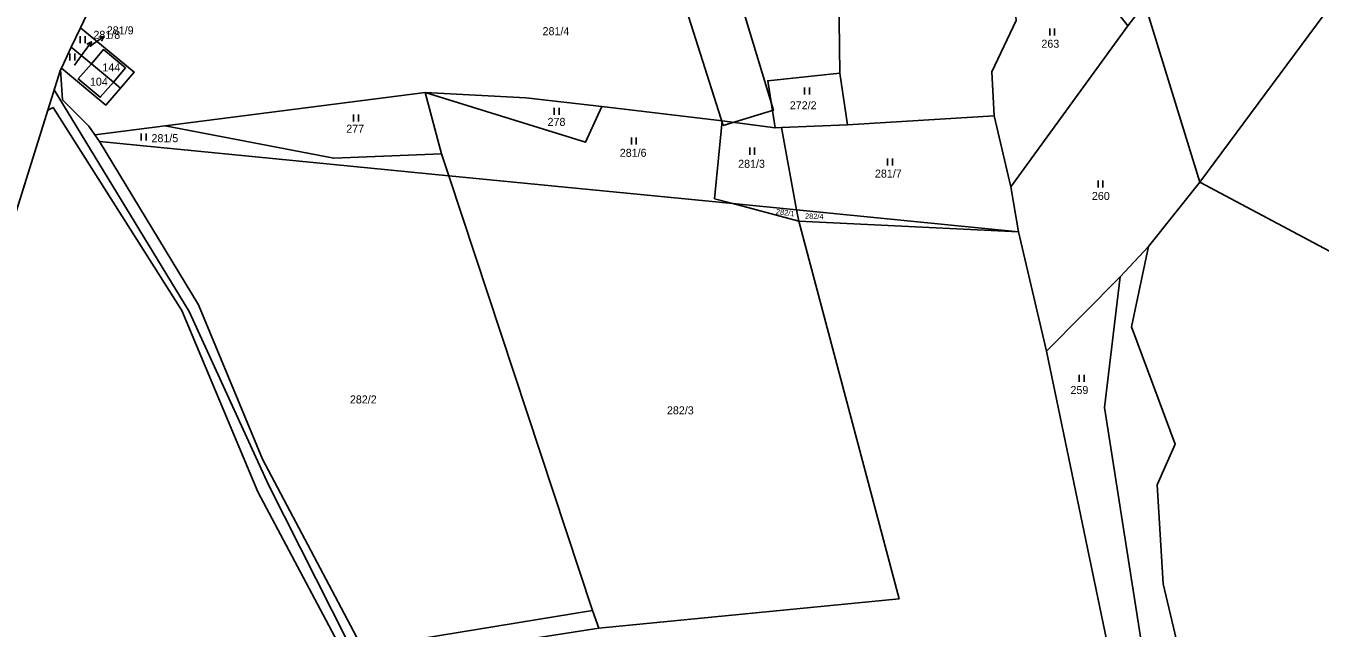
# Model space of a CAD drawing. Extents: x -590606 to -587796, y -1065936 to -1062515.
# Drawn here: x -589191 to -588916, y -1064752.6 to -1064624.7 of the extents above; entities that cross this region are included whole.
import ezdxf

# ---------------------------------------------------------------- set-up
doc = ezdxf.new("R2010")
doc.units = 0
for name, color, linetype in [('Cesty', 7, 'Continuous'), ('Parcela nároku', 7, 'Continuous'), ('Parcelní číslo', 7, 'Continuous'), ('Tok', 7, 'Continuous'), ('Vnější obvod_ Studené', 7, 'Continuous'), ('Vrstva 30', 7, 'Continuous')]:
    doc.layers.add(name, color=color, linetype=linetype)

msp = doc.modelspace()

# ---------------------------------------------------------------- linework, layer by layer
at = {"layer": 'Cesty'}
msp.add_lwpolyline([(-589184.99, -1064638.29), (-589156.28, -1064685.35), (-589139.47, -1064722.15), (-589122.5, -1064755.61), (-589105.35, -1064782.5), (-589087.98, -1064799.87), (-589067.31, -1064825.55), (-589029.84, -1064877.89), (-589010.25, -1064901.8), (-588993.22, -1064919.79), (-588983.42, -1064935.93), (-588980.16, -1064951.16), (-588977.69, -1065009.91), (-588977.48, -1065046.76), (-588981.79, -1065081.08), (-588987.44, -1065116.25), (-588996.39, -1065156.18), (-589000.35, -1065173.86), (-589006.25, -1065208.69), (-589010.09, -1065230.21), (-589013.59, -1065251.3), (-589016.6, -1065276.3)], dxfattribs=at)
at = {"layer": 'Parcela nároku'}
for points in [[(-589219.53, -1064748.72), (-589186.36, -1064642.57), (-589183.62, -1064634.01), (-589183.45, -1064633.66), (-589181.35, -1064629.23), (-589179.39, -1064625.08), (-589169.88, -1064604.99), (-589163.72, -1064594.94), (-589149.8, -1064577.36), (-589123.77, -1064546.13), (-589122.47, -1064544.56), (-589115.01, -1064533.6), (-589105.28, -1064518.51), (-589092.65, -1064498.9), (-589083.82, -1064476.76), (-589078.44, -1064456.79), (-589078.02, -1064448.81)], [(-589018.59, -1064595.36), (-589018.06, -1064634.7), (-589033.39, -1064636.33), (-589031.82, -1064646.35), (-589043.08, -1064644.87), (-589068.62, -1064641.84), (-589084.79, -1064639.98), (-589106.17, -1064638.82), (-589161.43, -1064645.92), (-589176.35, -1064647.81), (-589177.63, -1064646), (-589183.22, -1064640.41), (-589183.62, -1064634.01), (-589183.45, -1064633.66), (-589174, -1064641.5), (-589170.91, -1064637.91), (-589167.98, -1064634.49), (-589179.39, -1064625.08), (-589169.88, -1064604.99)], [(-589123.59, -1064757.72), (-589141.72, -1064723.62), (-589157.85, -1064685.09), (-589185.23, -1064641.99), (-589186.36, -1064642.57), (-589183.62, -1064634.01), (-589183.22, -1064640.41), (-589177.63, -1064646), (-589176.35, -1064647.81), (-589175.35, -1064649.22), (-589154.32, -1064683.93), (-589140.74, -1064716.67), (-589119.49, -1064756.86)]]:
    msp.add_lwpolyline(points, dxfattribs=at)
for points in [[(-588921.82, -1064576.81), (-588889.35, -1064537.12), (-588851.4, -1064545.12), (-588898.31, -1064599.49), (-588941.62, -1064657.84), (-588953.26, -1064619.99)], [(-588851.4, -1064545.12), (-588839.04, -1064546.13), (-588805.58, -1064554.11), (-588792.71, -1064559.39), (-588782.54, -1064564.66), (-588772.3, -1064573.34), (-588757.48, -1064588.92), (-588770.58, -1064594.99), (-588786.57, -1064605.7), (-588800.43, -1064621.56), (-588815.43, -1064642.06), (-588829.52, -1064669.09), (-588842.19, -1064696.66), (-588844.89, -1064709.35), (-588941.62, -1064657.84), (-588898.31, -1064599.49)], [(-588997.54, -1064571.27), (-589018.59, -1064595.36), (-589018.06, -1064634.7), (-589016.44, -1064645.68), (-588985.3, -1064643.81), (-588985.82, -1064634.41), (-588980.63, -1064623.57), (-588981.74, -1064609.85), (-588986.18, -1064590.18)], [(-588985.82, -1064634.41), (-588980.63, -1064623.57), (-588981.74, -1064609.85), (-588975.18, -1064601.25), (-588956.87, -1064624.68), (-588981.77, -1064658.84), (-588985.3, -1064643.81)], [(-588941.62, -1064657.84), (-588953.26, -1064619.99), (-588956.87, -1064624.68), (-588981.77, -1064658.84), (-588980.15, -1064668.39), (-588974.19, -1064693.78), (-588958.49, -1064677.96), (-588952.5, -1064671.53)], [(-589179.39, -1064625.08), (-589167.98, -1064634.49), (-589170.91, -1064637.91), (-589172.42, -1064636.61), (-589169.85, -1064633.6), (-589174.54, -1064629.73), (-589177.09, -1064632.75), (-589181.35, -1064629.23)], [(-589183.45, -1064633.66), (-589181.35, -1064629.23), (-589177.09, -1064632.75), (-589179.89, -1064635.96), (-589175.21, -1064639.84), (-589172.42, -1064636.61), (-589170.91, -1064637.91), (-589174, -1064641.5)], [(-589174.54, -1064629.73), (-589169.85, -1064633.6), (-589172.42, -1064636.61), (-589177.09, -1064632.75)], [(-589179.89, -1064635.96), (-589177.09, -1064632.75), (-589172.42, -1064636.61), (-589175.21, -1064639.84)], [(-589018.06, -1064634.7), (-589033.39, -1064636.33), (-589031.82, -1064646.35), (-589030.47, -1064646.29), (-589016.44, -1064645.68)], [(-589106.17, -1064638.82), (-589102.68, -1064651.85), (-589125.6, -1064652.78), (-589161.43, -1064645.92)], [(-589084.79, -1064639.98), (-589068.62, -1064641.84), (-589072.11, -1064649.41), (-589106.17, -1064638.82)], [(-589040.82, -1064662.43), (-589044.7, -1064661.39), (-589043.08, -1064644.87), (-589068.62, -1064641.84), (-589072.11, -1064649.41), (-589106.17, -1064638.82), (-589102.68, -1064651.85), (-589101.14, -1064656.51)], [(-589123.59, -1064757.72), (-589141.72, -1064723.62), (-589157.85, -1064685.09), (-589185.23, -1064641.99), (-589186.36, -1064642.57), (-589219.53, -1064748.72), (-589218.27, -1064765.02), (-589213.92, -1064786.57), (-589188.45, -1064839.84), (-589159.82, -1064824.9), (-589138.93, -1064817.47), (-589090.35, -1064802), (-589107.58, -1064783.08)], [(-589016.44, -1064645.68), (-588985.3, -1064643.81), (-588981.77, -1064658.84), (-588980.15, -1064668.39), (-589027.26, -1064663.76), (-589030.47, -1064646.29)], [(-589102.68, -1064651.85), (-589101.14, -1064656.51), (-589175.35, -1064649.22), (-589176.35, -1064647.81), (-589161.43, -1064645.92), (-589125.6, -1064652.78)], [(-589044.7, -1064661.39), (-589043.08, -1064644.87), (-589031.82, -1064646.35), (-589030.47, -1064646.29), (-589027.26, -1064663.76), (-589040.82, -1064662.43)], [(-589175.35, -1064649.22), (-589101.14, -1064656.51), (-589070.59, -1064748.83), (-589119.49, -1064756.86), (-589140.74, -1064716.67), (-589154.32, -1064683.93)], [(-589101.14, -1064656.51), (-589040.82, -1064662.43), (-589026.82, -1064666.18), (-589005.5, -1064746.34), (-589069.25, -1064752.55), (-589070.59, -1064748.83)], [(-588952.5, -1064671.53), (-588941.62, -1064657.84), (-588844.89, -1064709.35), (-588846.83, -1064718.35), (-588857.69, -1064752.58), (-588892.68, -1064777.43), (-588925.79, -1064796.63), (-588930.91, -1064779.48), (-588944.46, -1064764.13), (-588949.37, -1064743.17), (-588950.66, -1064722.17), (-588946.87, -1064713.5), (-588956.12, -1064688.59)], [(-589026.82, -1064666.18), (-589027.26, -1064663.76), (-589040.82, -1064662.43)], [(-589027.26, -1064663.76), (-588980.15, -1064668.39), (-589026.82, -1064666.18)], [(-589069.25, -1064752.55), (-589005.5, -1064746.34), (-589026.82, -1064666.18), (-588980.15, -1064668.39), (-588974.19, -1064693.78), (-588960.04, -1064761.8), (-588949.33, -1064805.81), (-588967.2, -1064808.27), (-589021.03, -1064800.12), (-589044.29, -1064798.14), (-589085.54, -1064800.35), (-589102.86, -1064782.92), (-589117.44, -1064760.08)], [(-588952.5, -1064671.53), (-588958.49, -1064677.96), (-588961.88, -1064705.69), (-588946.26, -1064804.98), (-588938.4, -1064802.77), (-588925.79, -1064796.63), (-588930.91, -1064779.48), (-588944.46, -1064764.13), (-588949.37, -1064743.17), (-588950.66, -1064722.17), (-588946.87, -1064713.5), (-588956.12, -1064688.59)], [(-588961.88, -1064705.69), (-588946.26, -1064804.98), (-588949.33, -1064805.81), (-588960.04, -1064761.8), (-588974.19, -1064693.78), (-588958.49, -1064677.96)], [(-589070.59, -1064748.83), (-589069.25, -1064752.55), (-589117.44, -1064760.08), (-589119.49, -1064756.86)]]:
    msp.add_lwpolyline(points, close=True, dxfattribs=at)
at = {"layer": 'Parcelní číslo'}
for p, q in [((-589176.87, -1064628.66), (-589174.42, -1064626.93)), ((-589178.84, -1064630.47), (-589177.09, -1064628.04)), ((-589177.34, -1064628.99), (-589176.87, -1064628.66)), ((-589180.68, -1064633.03), (-589178.84, -1064630.47))]:
    msp.add_line(p, q, dxfattribs=at)
for points in [[(-589175.53, -1064627.1), (-589174.42, -1064626.93), (-589174.95, -1064627.91)], [(-589178.08, -1064628.55), (-589177.09, -1064628.04), (-589177.27, -1064629.14)]]:
    msp.add_lwpolyline(points, dxfattribs=at)
at = {"layer": 'Tok'}
msp.add_lwpolyline([(-589050.66, -1064621.38), (-589039.58, -1064618.05), (-589032.2, -1064642.61), (-589042.85, -1064645.81)], close=True, dxfattribs=at)
at = {"layer": 'Vnější obvod_ Studené'}
for p, q in [((-589169.88, -1064604.99), (-589179.39, -1064625.08)), ((-589179.39, -1064625.08), (-589167.98, -1064634.49)), ((-589183.62, -1064634.01), (-589186.36, -1064642.57)), ((-589183.45, -1064633.66), (-589183.62, -1064634.01)), ((-589174, -1064641.5), (-589183.45, -1064633.66)), ((-589167.98, -1064634.49), (-589170.91, -1064637.91)), ((-589170.91, -1064637.91), (-589174, -1064641.5)), ((-589186.36, -1064642.57), (-589202.94, -1064695.64))]:
    msp.add_line(p, q, dxfattribs=at)
at = {"layer": 'Vrstva 30'}
for p, q in [((-589179.44, -1064626.84), (-589179.44, -1064628.34)), ((-589178.42, -1064628.34), (-589178.42, -1064626.84)), ((-588973.46, -1064625.26), (-588973.46, -1064626.76)), ((-588972.44, -1064626.76), (-588972.44, -1064625.26)), ((-589181.64, -1064630.54), (-589181.64, -1064632.04)), ((-589180.61, -1064632.04), (-589180.61, -1064630.54)), ((-589025.56, -1064637.77), (-589025.56, -1064639.27)), ((-589024.54, -1064639.27), (-589024.54, -1064637.77)), ((-589121.39, -1064643.49), (-589121.39, -1064644.99)), ((-589120.36, -1064644.99), (-589120.36, -1064643.49)), ((-589078.75, -1064642.1), (-589078.75, -1064643.6)), ((-589077.72, -1064643.6), (-589077.72, -1064642.1)), ((-589166.48, -1064647.51), (-589166.48, -1064649.01)), ((-589165.45, -1064649.01), (-589165.45, -1064647.51)), ((-589062.35, -1064648.39), (-589062.35, -1064649.89)), ((-589061.33, -1064649.89), (-589061.33, -1064648.39)), ((-589037.23, -1064650.54), (-589037.23, -1064652.04)), ((-589036.2, -1064652.04), (-589036.2, -1064650.54)), ((-589007.94, -1064652.86), (-589007.94, -1064654.36)), ((-589006.92, -1064654.36), (-589006.92, -1064652.86)), ((-588963.22, -1064657.54), (-588963.22, -1064659.04)), ((-588962.2, -1064659.04), (-588962.2, -1064657.54)), ((-588967.23, -1064698.76), (-588967.23, -1064700.26)), ((-588966.2, -1064700.26), (-588966.2, -1064698.76))]:
    msp.add_line(p, q, dxfattribs=at)

# ---------------------------------------------------------------- texts
at = {"layer": 'Parcela nároku'}
for s, height, p in [('281/4', 1.7, (-589081.23, -1064626.66)), ('281/9', 0.1, (-589177.34, -1064628.99)), ('263', 1.7, (-588975.26, -1064629.33)), ('144', 1.7, (-589174.76, -1064634.36)), ('281/8', 0.1, (-589180.68, -1064633.03)), ('104', 1.7, (-589177.39, -1064637.39)), ('272/2', 1.7, (-589028.71, -1064642.41)), ('277', 1.7, (-589122.94, -1064647.37)), ('278', 1.7, (-589080.17, -1064645.92)), ('281/5', 1.7, (-589164.31, -1064649.38)), ('281/6', 1.7, (-589064.83, -1064652.49)), ('281/3', 1.7, (-589039.68, -1064654.82)), ('281/7', 1.7, (-589010.62, -1064656.9)), ('260', 1.7, (-588964.53, -1064661.65)), ('259', 1.7, (-588969.08, -1064702.86)), ('282/2', 1.7, (-589122.16, -1064704.86)), ('282/3', 1.7, (-589054.81, -1064707.17))]:
    msp.add_text(s, height=height, dxfattribs=at).set_placement(p)
for s, rotation, p in [('282/1', 352.6088, (-589031.71, -1064664.65)), ('282/4', 358.1101, (-589025.49, -1064665.62))]:
    msp.add_text(s, height=1.14, rotation=rotation, dxfattribs=at).set_placement(p)
at = {"layer": 'Parcelní číslo'}
for s, p in [('281/8', (-589176.65, -1064627.43)), ('281/9', (-589173.8, -1064626.49))]:
    msp.add_text(s, height=1.7, dxfattribs=at).set_placement(p)

doc.saveas('drawing.dxf')
